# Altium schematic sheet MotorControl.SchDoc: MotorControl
size A4; DocumentNumber: MB1144; Revision: C-02; SheetNumber: 23; SheetTotal: 25; Project: STM32L476G-EVAL
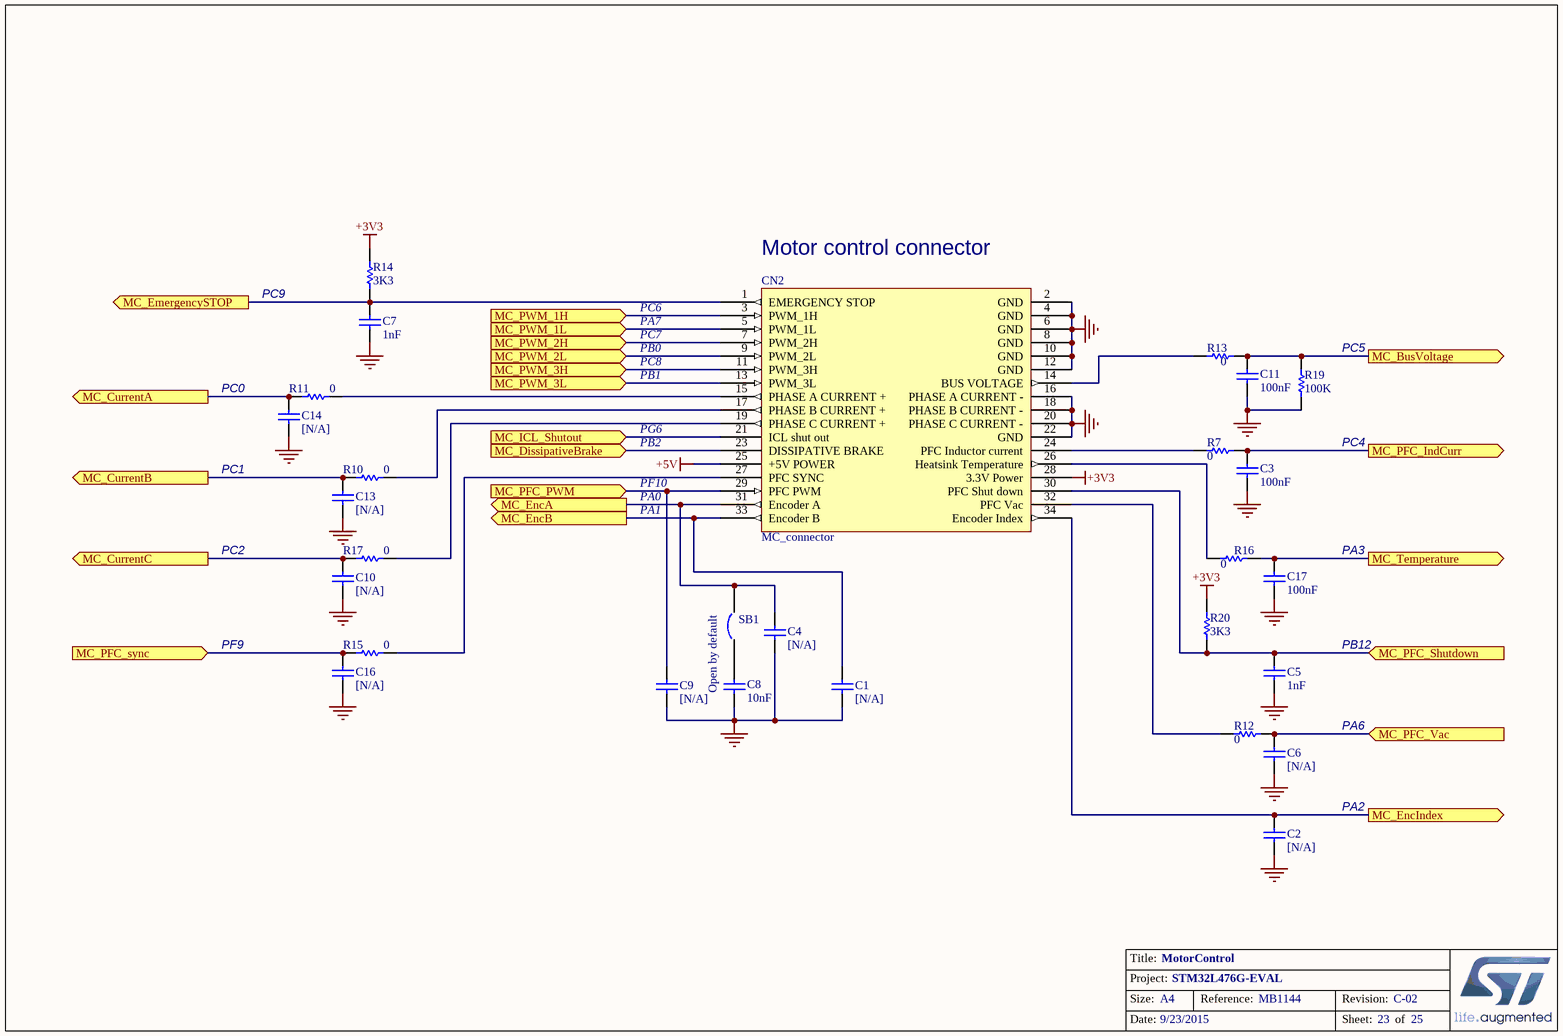
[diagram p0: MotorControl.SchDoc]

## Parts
C1  [N/A]  [0603C]
C2  [N/A]  [0603C]
C3  100nF  [0402C]
C4  [N/A]  [0603C]
C5  1nF  [0402C]
C6  [N/A]  [0603C]
C7  1nF  [0402C]
C8  10nF  [0402C]
C9  [N/A]  [0603C]
C10  [N/A]  [0603C]
C11  100nF  [0402C]
C13  [N/A]  [0603C]
C14  [N/A]  [0603C]
C16  [N/A]  [0603C]
C17  100nF  [0402C]
CN2  MC_connector  [IDC34S]
R7  0  [0603R]
R10  0  [0603R]
R11  0  [0603R]
R12  0  [0603R]
R13  0  [0603R]
R14  3K3  [0402R]
R15  0  [0603R]
R16  0  [0603R]
R17  0  [0603R]
R19  100K  [0402R]
R20  3K3  [0402R]
SB1  Open by default  [SB_0603]

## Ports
MC_BusVoltage (out), MC_CurrentA (out), MC_CurrentB (out), MC_CurrentC (out), MC_DissipativeBrake (in), MC_EmergencySTOP (out), MC_EncA (out), MC_EncB (out), MC_EncIndex (out), MC_ICL_Shutout (in), MC_PFC_IndCurr (out), MC_PFC_PWM (in), MC_PFC_Shutdown (in), MC_PFC_sync (in), MC_PFC_Vac (in), MC_PWM_1H (in), MC_PWM_1L (in), MC_PWM_2H (in), MC_PWM_2L (in), MC_PWM_3H (in), MC_PWM_3L (in), MC_Temperature (out)

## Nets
+3V3: CN2.28(3.3V_Power) R14.2 R20.2
+5V: CN2.25(+5V_POWER)
GND: C1.1 C2.1 C3.2 C4.1 C5.1 C6.1 C7.1 C8.2 C9.1 C10.1 C11.2 C13.1 C14.1 C16.1 C17.2 CN2.2(GND) CN2.4(GND) CN2.6(GND) CN2.8(GND) CN2.10(GND) CN2.12(GND) CN2.16(PHASE_A_CURRENT_-) CN2.18(PHASE_B_CURRENT_-) CN2.20(PHASE_C_CURRENT_-) CN2.22(GND) R19.2
MC_BusVoltage: C11.1 R13.2 R19.1 ; port MC_BusVoltage
MC_CurrentA: C14.2 R11.1 ; port MC_CurrentA
MC_CurrentB: C13.2 R10.1 ; port MC_CurrentB
MC_CurrentC: C10.2 R17.1 ; port MC_CurrentC
MC_DissipativeBrake: CN2.23(DISSIPATIVE_BRAKE) ; port MC_DissipativeBrake
MC_EmergencySTOP: C7.2 CN2.1(EMERGENCY_STOP) R14.1 ; port MC_EmergencySTOP
MC_EncA: C4.2 CN2.31(Encoder_A) SB1.2 ; port MC_EncA
MC_EncB: C1.2 CN2.33(Encoder_B) ; port MC_EncB
MC_EncIndex: C2.2 CN2.34(Encoder_Index) ; port MC_EncIndex
MC_ICL_Shutout: CN2.21(ICL_shut_out) ; port MC_ICL_Shutout
MC_PFC_IndCurr: C3.1 R7.2 ; port MC_PFC_IndCurr
MC_PFC_PWM: C9.2 CN2.29(PFC_PWM) ; port MC_PFC_PWM
MC_PFC_Shutdown: C5.2 CN2.30(PFC_Shut_down) R20.1 ; port MC_PFC_Shutdown
MC_PFC_sync: C16.2 R15.1 ; port MC_PFC_sync
MC_PFC_Vac: C6.2 R12.2 ; port MC_PFC_Vac
MC_PWM_1H: CN2.3(PWM_1H) ; port MC_PWM_1H
MC_PWM_1L: CN2.5(PWM_1L) ; port MC_PWM_1L
MC_PWM_2H: CN2.7(PWM_2H) ; port MC_PWM_2H
MC_PWM_2L: CN2.9(PWM_2L) ; port MC_PWM_2L
MC_PWM_3H: CN2.11(PWM_3H) ; port MC_PWM_3H
MC_PWM_3L: CN2.13(PWM_3L) ; port MC_PWM_3L
MC_Temperature: C17.1 R16.2 ; port MC_Temperature
NetC8_1: C8.1 SB1.1
NetCN2_14: CN2.14(BUS_VOLTAGE) R13.1
NetCN2_15: CN2.15(PHASE_A_CURRENT_+) R11.2
NetCN2_17: CN2.17(PHASE_B_CURRENT_+) R10.2
NetCN2_19: CN2.19(PHASE_C_CURRENT_+) R17.2
NetCN2_24: CN2.24(PFC_Inductor_current) R7.1
NetCN2_26: CN2.26(Heatsink_Temperature) R16.1
NetCN2_27: CN2.27(PFC_SYNC) R15.2
NetCN2_32: CN2.32(PFC_Vac) R12.1

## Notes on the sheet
- PC9
- PC6
- (near CN2) Motor control connector
- PA7
- PB0
- PB1
- PC7
- PC8
- (near R19) PC5
- PC0
- PG6
- PB2
- PC4
- PC1
- PA1
- PA0
- PF10
- PC2
- PA3
- PF9
- PB12
- PA6
- PA2

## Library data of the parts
C1 C2 C4 C6 C9 C10 C13 C14 C16 = cap: Capacitor; Value: 100pF; Ordered by: Subcon; ECCN_US/EU: NA; Fitted: NO
C3 C11 C17 = Cap: Capacitor; Value: 10nF; Ordered by: Subcon; ECCN_US/EU: NA
C5 C7 C8 = CAP: Capacitor; Value: 100pF; Ordered by: Subcon; ECCN_US/EU: NA
CN2 = MC_connector_1: Ordered by: Subcon; Comments: Motor Control conn.; ECCN_US/EU: NA
R7 R10-R17 R20 = Res1: Resistor; Value: 1K; Ordered by: Subcon; ECCN_US/EU: NA
R19 = res1: Resistor; Value: 1K; Ordered by: Subcon; ECCN_US/EU: NA
SB1 = Circuit Breaker: Ordered by: Subcon; Comments: Solder bridge; Fitted: NO; ECCN_US/EU: NA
